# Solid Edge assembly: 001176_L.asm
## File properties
Last saved by: morva
Revision: 33
Application: Solid Edge
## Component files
001176-12_L.par
001176-6_L.par
001176-3_L.par
001176-8_L.par
001176-4_L.par
001176-5_L.par
001176-1_L.par
001176-10_L.par
001176-7_L.par
001176-2_L.par
001176-13_L.par
001176-11_L.par
001176-9_L.par
